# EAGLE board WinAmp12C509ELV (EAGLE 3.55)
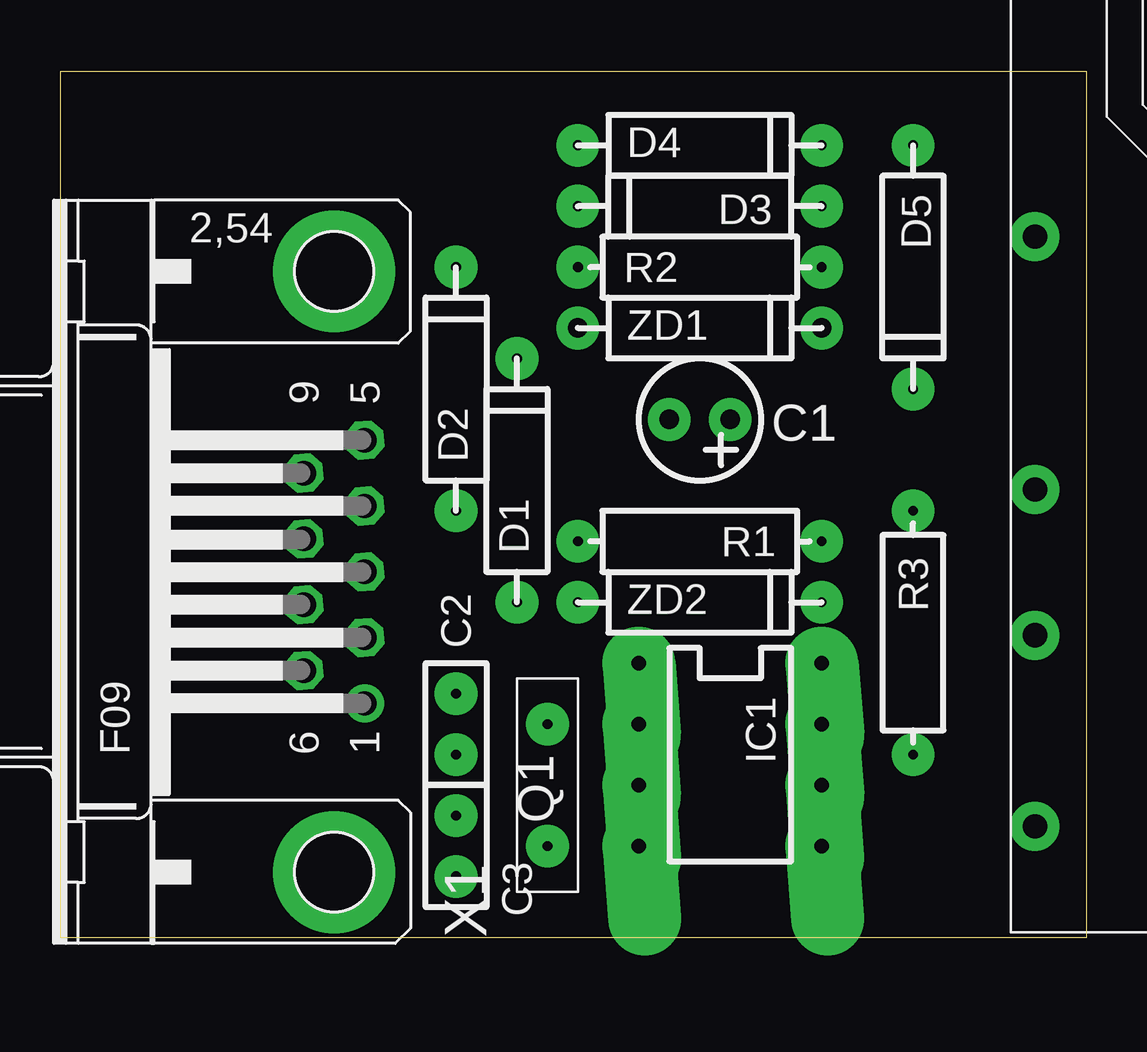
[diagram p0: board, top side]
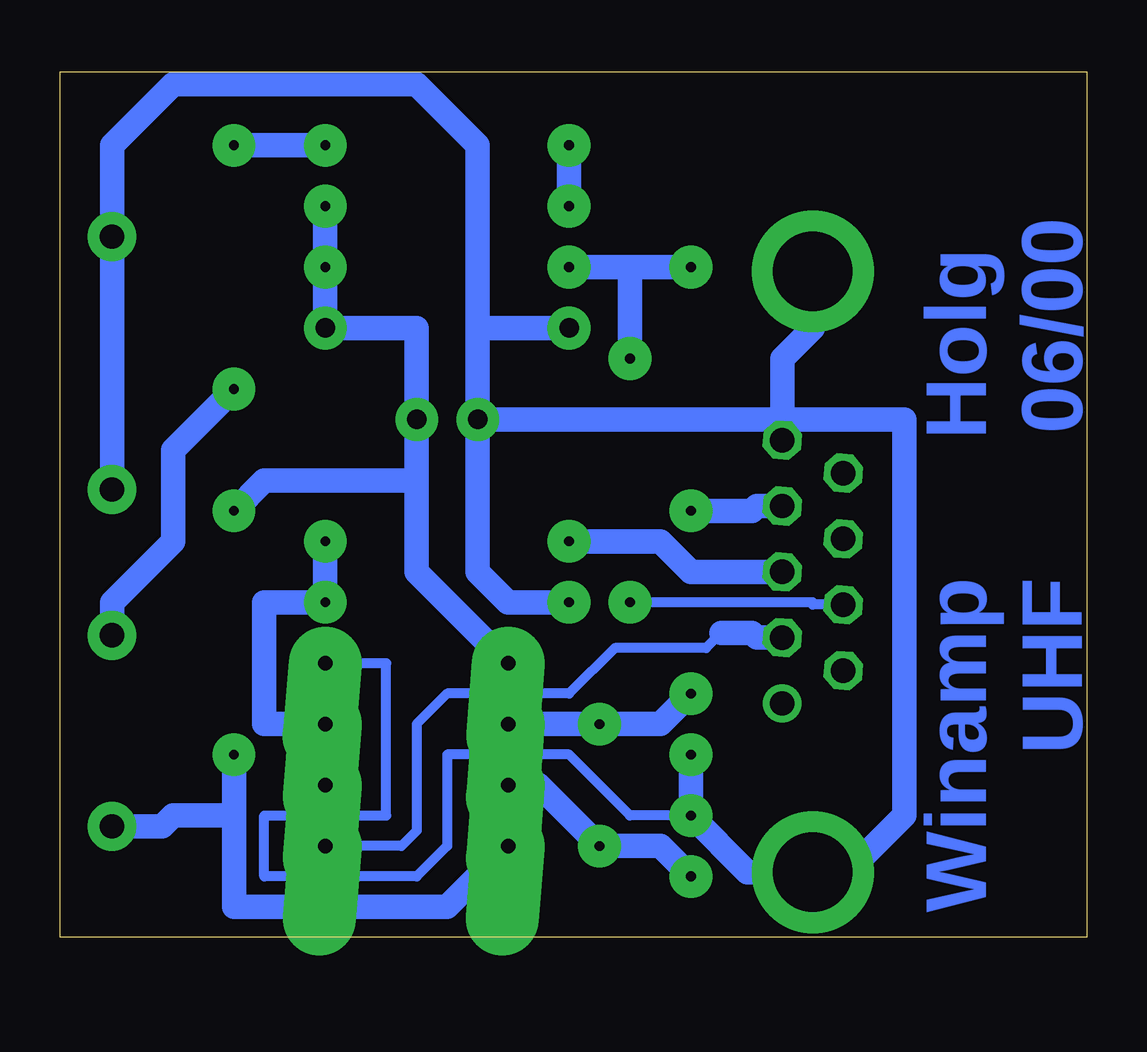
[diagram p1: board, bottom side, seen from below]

Size 42.81 x 36.08 mm. Coordinates in mm from the lower left corner, seen from the top.
Outline: 0,0 42.81,0 42.81,36.08 0,36.08 0,0
Copper layers used: Bottom

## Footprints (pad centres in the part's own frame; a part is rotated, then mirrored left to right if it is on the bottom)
KO01 = drill 0.813 pad 1.778 round:  0,0;  2.54,0
RM2,5 = drill 0.406 pad 1.778 round:  0,0;  2.54,0
O04 = drill 0.406 pad 1.778 round:  0,0;  10.16,0
L-8B = drill 0.61 pad 3.048 offset:  0,0;  2.54,0;  5.08,0;  7.62,0;  7.62,7.62;  5.08,7.62;  2.54,7.62;  0,7.62
V433RE = drill 1.016 pad 2.032 round: 1 10.54,0; OD 24.58,0;  0,0;  16.62,0
ARZ_ST = drill 0.406 pad 1.778 round:  0,0;  5.08,0
S04 = drill 0.406 pad 1.778 round:  0,0;  10.16,0
9HP = drill 1.016 pad 1.6 round:  -5.486,-1.27 | drill 1.016 pad 1.6 octagon:  -2.743,-1.27;  0,-1.27;  2.743,-1.27;  5.486,-1.27;  -4.115,1.27;  -1.372,1.27;  1.372,1.27;  4.115,1.27 | drill 3.302 pad 5.08 round:  -12.522,0;  12.522,0
O04' = drill 0.813 pad 1.778 round:  0,0;  10.16,0

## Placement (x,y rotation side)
C1  4u7  [KO01]  27.94,21.59 180 top
C2  27p  [RM2,5]  16.51,7.62 90 top
C3  27p  [RM2,5]  16.51,5.08 270 top
D1  1N4148  [O04]  19.05,13.97 90 top
D2  1N4148  [O04]  16.51,17.78 90 top
D3  1N4148  [O04]  31.75,30.48 180 top
D4  1N4148  [O04]  21.59,33.02 0 top
D5  1N4148  [O04]  35.56,33.02 270 top
IC1  12C509P  [L-8B]  24.13,11.43 270 top
M1  ELV433REC  [V433RE]  40.64,29.21 270 top
Q1  4MHz  [ARZ_ST]  20.32,8.89 270 top
R1  47k  [S04]  31.75,16.51 180 top
R2  1k  [S04]  21.59,27.94 0 top
R3  47k  [S04]  35.56,17.78 270 top
X1  F09HP  [9HP]  11.43,15.24 90 top
ZD1  5V1  [O04']  21.59,25.4 0 top
ZD2  5V1  [O04]  21.59,13.97 0 top

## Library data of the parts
C1 ZD1 = holgeins
C2 C3 D1-D5 IC1 Q1 R1-R3 ZD2 = holg_plt
M1 = ic_holg3
X1 = subd-a

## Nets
GND: C1. C2. C3. IC1. M1. M1.1 X1. ZD1. ZD2.
N$1: IC1. R1. ZD2.
N$2: C1. D3. IC1. R2. R3. ZD1.
N$3: D2. X1.
N$4: D1. X1.
N$6: D1. D2. R2.
N$7: IC1. M1.OD R3.
N$8: C3. IC1. Q1.
N$9: C2. IC1. Q1.
N$10: D3. D4.
N$11: D4. D5.
N$12: D5. M1.
RXD: IC1. X1.
TXD: R1. X1.

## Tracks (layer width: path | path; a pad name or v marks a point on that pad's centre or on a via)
GND
  Bottom 0.406: 12.7,21.59 12.7,20.73 | 9.98,2.72 11.43,2.72 | 11.43,25.4 X1. | IC1. 29.21,11.43 29.21,5.08 34.29,5.08 34.29,2.54 27.94,2.54 26.67,3.81 26.67,7.62 21.59,7.62 19.05,5.08 16.51,5.08
  Bottom 1.016: C1. 25.4,25.4 21.59,25.4 | 16.51,7.62 16.51,5.08 14.15,2.72 11.43,2.72 | 21.59,13.97 24.13,13.97 25.4,15.24 C1. | 12.7,21.59 7.62,21.59 7.62,5.08 9.98,2.72 | 11.43,25.4 12.7,24.13 12.7,21.59 | 12.7,21.59 C1. | C1. 25.4,33.02 27.94,35.56 38.1,35.56 40.64,33.02 40.64,29.21 M1.1
N$1
  Bottom 1.016: 31.75,16.51 ZD2. 34.29,13.97 34.29,8.89 31.75,8.89
N$2
  Bottom 1.016: 27.94,19.05 27.94,15.24 24.13,11.43 | 27.94,19.05 27.94,21.59 27.94,25.4 ZD1. R2. 31.75,30.48 | 35.56,17.78 34.29,19.05 27.94,19.05
N$3
  Bottom 1.016: 12.7,17.98 13.77,17.98 13.97,17.78 16.51,17.78
N$4
  Bottom 0.406: 19.05,13.97 11.43,13.97 11.43,13.87 10.16,13.87
N$6
  Bottom 1.016: 19.05,27.94 21.59,27.94 | 19.05,27.94 D2. | D1. 19.05,27.94
N$7
  Bottom 1.016: 24.13,3.81 26.67,1.27 35.56,1.27 35.56,5.08 | M1.OD 38.55,4.63 38.1,5.08 35.56,5.08 | 35.56,5.08 R3.
N$8
  Bottom 1.016: C3. 17.78,3.81 Q1. 22.86,6.35 24.13,6.35
N$9
  Bottom 1.016: 24.13,8.89 20.32,8.89 17.78,8.89 C2.
N$10
  Bottom 1.016: D3. 21.59,33.02
N$11
  Bottom 1.016: D4. 35.56,33.02
N$12
  Bottom 1.016: D5. 38.1,20.32 38.1,16.51 40.64,13.97 M1.
RXD
  Bottom 0.406: 31.75,3.81 28.57,3.81 27.94,4.45 27.94,8.89 26.67,10.16 21.59,10.16 19.68,12.06 15.88,12.06 15.24,12.7
  Bottom 1.016: 12.7,12.5 13.77,12.5 13.97,12.7 15.24,12.7
TXD
  Bottom 1.016: 12.7,15.24 16.51,15.24 17.78,16.51 R1.

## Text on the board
Bottom: 06/00 | Holg | UHF | Winamp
